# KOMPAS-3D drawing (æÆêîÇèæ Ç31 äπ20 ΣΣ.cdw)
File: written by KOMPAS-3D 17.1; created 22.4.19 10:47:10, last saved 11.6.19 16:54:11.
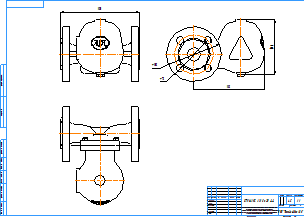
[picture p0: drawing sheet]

Sheet 1: A2, landscape

Title block, sheet 1: name: СТИМАКС А31 Ду20 фф; material: Внимание! Данный продукт является объектом авторского права ООО «Торговый Дом АДЛ». / Запрещается изменение, копирование, распространение / (в том числе путем копирования на другие сайты и ресурсы в Интернете) / или любое иное использование информации и объектов без предварительного / согласия правообладателя (ООО «Торговый Дом АДЛ»).; mass: 4,5; sheets: 1; organisation: ООО "Торговый дом АДЛ"; sheet format: A2; stored path: \\adlc.lan\data\АДЛ_ПКД\3D-модели\ADL production\Конденсатоотводчики СТИМАКС\Поплавковые\Серия А31\KOMPAS 2D\СТИМАКС А31 Ду20 фф.cdw

Views: Вид 1, Проекционный вид 2, Проекционный вид 3
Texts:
  user
Dimensions and other numbers on the sheet: 150; 135; 105; 104; 75; 1:1; 1; 4,5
